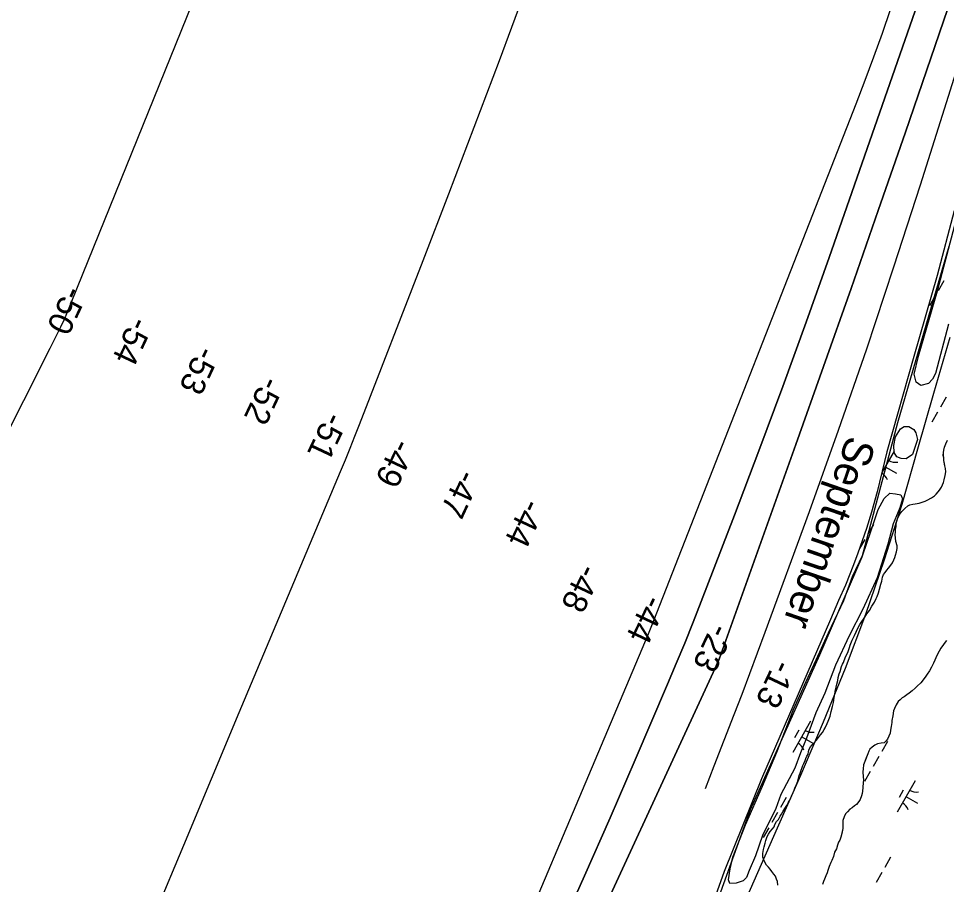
# Model space of a CAD drawing. Extents: x 3930721 to 3950824, y 220441 to 242861.
# Drawn here: x 3941164 to 3942447, y 230620 to 231818 of the extents above; entities that cross this region are included whole.
import ezdxf

# ---------------------------------------------------------------- set-up
doc = ezdxf.new("R2010")
doc.units = 0
for name, color, linetype in [('V-RIVR-EDGE', 7, 'Continuous'), ('V-RIVR-IDEN', 7, 'Continuous'), ('V-RIVR-JETY', 7, 'Continuous'), ('V-RIVR-RANG', 7, 'Continuous'), ('V-RRAP-FSHR', 7, 'Continuous'), ('V-TOPO-DPTH', 7, 'Continuous'), ('V-TOPO-MAJR', 7, 'Continuous'), ('V-TOPO-MINR', 7, 'Continuous'), ('V-TOPO-SHOR', 7, 'Continuous'), ('V-WETL-SWMP', 7, 'Continuous')]:
    doc.layers.add(name, color=color, linetype=linetype)

msp = doc.modelspace()

# ---------------------------------------------------------------- linework, layer by layer
at = {"layer": 'V-RIVR-EDGE'}
msp.add_lwpolyline([(3942450.4, 231502.1), (3942379.5, 231258.1), (3942329.9, 231072.3), (3942271.7, 230936.9), (3942175.7, 230722.8), (3942101.7, 230518.2), (3942078.1, 230444.2), (3941958.4, 230211.9), (3941798.6, 229866.4), (3941745.1, 229747.5)], dxfattribs=at)
at = {"layer": 'V-RIVR-JETY'}
for points in [[(3942450, 231394.6), (3942431.8, 231326.4), (3942428, 231318.9), (3942422.5, 231312.6), (3942411.9, 231310.1), (3942405.2, 231314.4), (3942402.7, 231325.7), (3942408.4, 231350.6), (3942435, 231440.9), (3942463, 231547.3)], [(3942407.2, 231235.3), (3942400.3, 231214.4), (3942391.3, 231208.4), (3942384.6, 231208.8), (3942378.7, 231211.1), (3942374.7, 231217.3), (3942374.2, 231226.7), (3942376.5, 231239), (3942383.4, 231250), (3942388.9, 231253.2), (3942395.2, 231253.3), (3942401.9, 231249), (3942404.7, 231244.4), (3942407.2, 231235.3)], [(3942211, 230724.5), (3942192.5, 230687.4), (3942183, 230659.3), (3942174.5, 230638.8), (3942170.7, 230629.3), (3942166, 230624.6), (3942156.2, 230621.3), (3942147.6, 230620.8), (3942145.6, 230625.9), (3942148.2, 230641.3), (3942151.9, 230657.4), (3942169.2, 230702.1), (3942192.6, 230755.4), (3942212.6, 230802.8), (3942235.6, 230861.6), (3942253.3, 230900.3), (3942267.1, 230930.3), (3942284.1, 230967.9), (3942305.2, 231012.5), (3942317.1, 231045.7), (3942331.7, 231075.7), (3942342.4, 231107.7), (3942352.7, 231138.4), (3942360.8, 231153.5), (3942369, 231161), (3942376.5, 231159.9), (3942384, 231158.8), (3942386.4, 231153.3), (3942382.6, 231140.7), (3942373.4, 231118.6), (3942366.2, 231090.6), (3942351.3, 231043.7), (3942331.7, 231000.6), (3942312.4, 230963.4), (3942293.9, 230923.1), (3942279, 230884.1), (3942266.7, 230857.2), (3942253.7, 230822.1), (3942245.2, 230801.5), (3942237.6, 230780.6), (3942218.3, 230744.2), (3942211, 230724.5)]]:
    msp.add_lwpolyline(points, dxfattribs=at)
at = {"layer": 'V-RRAP-FSHR'}
for points in [[(3942407.4, 231222.5), (3942429.6, 231299.3), (3942452.2, 231376.7)], [(3942019.7, 230258.7), (3942052.3, 230331.9), (3942084.4, 230405.7), (3942116.7, 230478.2), (3942149.1, 230551.4), (3942181.3, 230624.6), (3942213.6, 230697.8), (3942245.9, 230771), (3942277.3, 230844.6), (3942307.6, 230918.6), (3942335.7, 230993.5), (3942361.7, 231069.1), (3942385.7, 231145.6), (3942407.4, 231222.5)]]:
    msp.add_lwpolyline(points, dxfattribs=at)
at = {"layer": 'V-TOPO-DPTH'}
for points in [[(3942453.9, 231845.5), (3942443.3, 231814), (3942390.4, 231660.4), (3942352.9, 231552.2), (3942315.2, 231444.1), (3942277.2, 231336.1), (3942238.9, 231228.2), (3942137.6, 230944.3), (3942135.2, 230937.9), (3942132.6, 230931.4), (3942129.9, 230925.1), (3942127.1, 230918.8), (3941921, 230472.3), (3941888, 230401.2), (3941854.9, 230330.1), (3941821.4, 230259.2), (3941787.8, 230188.4), (3941758.8, 230127.6), (3941739.5, 230087.3), (3941720.2, 230046.9), (3941700.9, 230006.6), (3941681.6, 229966.3), (3941338.2, 229249.8)], [(3941491.1, 229651.3), (3941540.1, 229754), (3941663.9, 230015.8), (3941675, 230039.2), (3941685.9, 230062.7), (3941696.9, 230086.2), (3941707.7, 230109.7), (3941874.3, 230471.6), (3941910.6, 230551.4), (3941946.5, 230631.4), (3941981.8, 230711.7), (3942016.7, 230792.2), (3942061.5, 230896.6), (3942073.5, 230925.1), (3942085.4, 230953.6), (3942096.8, 230982.4), (3942108.1, 231011.2), (3942154.1, 231130.7), (3942187.7, 231219.4), (3942220.8, 231308.4), (3942253.1, 231397.7), (3942284.8, 231487.2), (3942410.7, 231848.7)], [(3942410.7, 231848.7), (3942284.8, 231487.2), (3942253.1, 231397.7), (3942220.8, 231308.4), (3942187.7, 231219.4), (3942154.1, 231130.7), (3942108.1, 231011.2), (3942096.8, 230982.4), (3942085.4, 230953.6), (3942073.5, 230925.1), (3942061.5, 230896.6), (3942016.7, 230792.2), (3941981.8, 230711.7), (3941946.5, 230631.4), (3941910.6, 230551.4), (3941874.3, 230471.6), (3941707.7, 230109.7), (3941696.9, 230086.2), (3941685.9, 230062.7), (3941675, 230039.2), (3941663.9, 230015.8), (3941540.1, 229754), (3941491.1, 229651.3)], [(3941769.9, 230338.3), (3942035, 230966.4), (3942036.9, 230971), (3942038.8, 230975.5), (3942040.7, 230980.1), (3942042.5, 230984.8), (3942322.4, 231699.8), (3942334.8, 231732.3), (3942346.9, 231764.8), (3942358.6, 231797.5), (3942369.9, 231830.3)], [(3941769.9, 230338.3), (3942035, 230966.4), (3942036.9, 230971), (3942038.8, 230975.5), (3942040.7, 230980.1), (3942042.5, 230984.8), (3942322.4, 231699.8), (3942334.8, 231732.3), (3942346.9, 231764.8), (3942358.6, 231797.5), (3942369.9, 231830.3)]]:
    msp.add_lwpolyline(points, dxfattribs=at)
at = {"layer": 'V-TOPO-MAJR'}
for points in [[(3941426.2, 231894.7), (3941229.1, 231406.6), (3941228.6, 231405.4), (3941228.3, 231404.8), (3941228, 231404.2), (3941221.5, 231390.5), (3941217.9, 231383.1), (3941214.3, 231375.7), (3941210.6, 231368.3), (3941206.9, 231361), (3940805.4, 230563.5), (3940792.7, 230537.9), (3940780.1, 230512.3), (3940767.7, 230486.5), (3940755.5, 230460.7), (3940592.2, 230110.7), (3940552.6, 230025.6), (3940513.2, 229940.4), (3940474.1, 229855.1), (3940435.2, 229769.8), (3940389.8, 229670)], [(3941354, 230582.4), (3941392.3, 230674.1), (3941430.6, 230765.7), (3941469, 230857.3), (3941609.1, 231190.9), (3941615.8, 231207.2), (3941622.4, 231223.4), (3941628.9, 231239.7), (3941635.4, 231256.1), (3941723.4, 231482.8), (3941758.9, 231575), (3941794.1, 231667.3), (3941828.7, 231759.8), (3941863, 231852.4)]]:
    msp.add_lwpolyline(points, dxfattribs=at)
at = {"layer": 'V-TOPO-MINR'}
for points in [[(3941338.2, 229249.8), (3941681.6, 229966.3), (3941700.9, 230006.6), (3941720.2, 230046.9), (3941739.5, 230087.3), (3941758.8, 230127.6), (3941787.8, 230188.4), (3941821.4, 230259.2), (3941854.9, 230330.1), (3941888, 230401.2), (3941921, 230472.3), (3942127.1, 230918.8), (3942129.9, 230925.1), (3942132.6, 230931.4), (3942135.2, 230937.9), (3942137.6, 230944.3), (3942238.9, 231228.2), (3942277.2, 231336.1), (3942315.2, 231444.1), (3942352.9, 231552.2), (3942390.4, 231660.4), (3942443.3, 231814), (3942453.9, 231845.5)], [(3941491.1, 229651.3), (3941540.1, 229754), (3941663.9, 230015.8), (3941675, 230039.2), (3941685.9, 230062.7), (3941696.9, 230086.2), (3941707.7, 230109.7), (3941874.3, 230471.6), (3941910.6, 230551.4), (3941946.5, 230631.4), (3941981.8, 230711.7), (3942016.7, 230792.2), (3942061.5, 230896.6), (3942073.5, 230925.1), (3942085.4, 230953.6), (3942096.8, 230982.4), (3942108.1, 231011.2), (3942154.1, 231130.7), (3942187.7, 231219.4), (3942220.8, 231308.4), (3942253.1, 231397.7), (3942284.8, 231487.2), (3942410.7, 231848.7)], [(3942113.7, 230752.2), (3942125.9, 230783.8), (3942153.4, 230854.6), (3942164.4, 230883), (3942175.2, 230911.4), (3942185.9, 230939.9), (3942196.4, 230968.5), (3942257.5, 231135.6), (3942297.7, 231248), (3942336.9, 231360.8), (3942374.6, 231474.1), (3942411.3, 231587.7), (3942493.9, 231849.4)], [(3941769.9, 230338.3), (3942035, 230966.4), (3942036.9, 230971), (3942038.8, 230975.5), (3942040.7, 230980.1), (3942042.5, 230984.8), (3942322.4, 231699.8), (3942334.8, 231732.3), (3942346.9, 231764.8), (3942358.6, 231797.5), (3942369.9, 231830.3)]]:
    msp.add_lwpolyline(points, dxfattribs=at)
at = {"layer": 'V-TOPO-SHOR'}
for points in [[(3942270.3, 230822.9), (3942273.1, 230826.7), (3942275.5, 230829.9), (3942277.9, 230833.8), (3942279.6, 230836.2), (3942282.3, 230842.2), (3942283.7, 230845.7), (3942286.1, 230852.4), (3942287.8, 230859), (3942289.4, 230866), (3942291.1, 230871.3), (3942291.4, 230874.5), (3942291.8, 230878.3), (3942292.8, 230882.9), (3942293.4, 230886.4), (3942294.8, 230892.7), (3942295.4, 230896.5), (3942296.8, 230901.8), (3942297.4, 230906), (3942298.8, 230910.9), (3942300.1, 230914.4), (3942302.2, 230921), (3942303.2, 230924.2), (3942304.9, 230926.7), (3942307.6, 230934.4), (3942310.7, 230940.7), (3942313.1, 230947.4), (3942314.1, 230950.5), (3942316.8, 230957.5), (3942318.2, 230960.4), (3942319.9, 230964.2), (3942321.3, 230967), (3942323.3, 230971.2), (3942325.7, 230976.2), (3942327.4, 230979.3), (3942330.2, 230983.5), (3942332.2, 230986.7), (3942334.3, 230989.2), (3942337.1, 230993.8), (3942340.5, 230998.7), (3942344, 231004.7), (3942347.7, 231010.3), (3942349.8, 231015.2), (3942351.2, 231018), (3942353.2, 231022.9), (3942354.5, 231028.2), (3942356.6, 231035.2), (3942357.6, 231039.1), (3942358.9, 231044.7), (3942360.3, 231048.5), (3942362.4, 231051), (3942364.8, 231054.2), (3942367.2, 231057), (3942370.3, 231061.2), (3942372.4, 231064.7), (3942374.4, 231068.6), (3942375.8, 231072.1), (3942376.8, 231075.2), (3942378.1, 231079.8), (3942378.8, 231084.4), (3942378.8, 231088.2), (3942377.3, 231094.1), (3942376.9, 231099), (3942376.2, 231103.2), (3942376.8, 231107.1), (3942376.8, 231110.9), (3942377.4, 231114.4), (3942377.8, 231118.2), (3942378.4, 231122.1), (3942380.1, 231127), (3942382.9, 231131.9), (3942385.6, 231135.5), (3942389.4, 231139.7), (3942393.9, 231143.6), (3942396.7, 231145), (3942400.5, 231145.7), (3942403.7, 231146.1), (3942409.6, 231147.2), (3942413.5, 231148.3), (3942417.6, 231149.8), (3942420.4, 231151.2), (3942426.3, 231154.4), (3942430.5, 231157.2), (3942432.9, 231159.7), (3942435.7, 231162.9), (3942437.7, 231165.3), (3942440.2, 231169.2), (3942442.9, 231175.5), (3942444.2, 231179.4), (3942445.6, 231185.3), (3942446.2, 231190.6), (3942445.8, 231195.1), (3942445.1, 231198.6), (3942444.4, 231202.5), (3942443.6, 231206.3), (3942443.6, 231209.4), (3942442.9, 231213.6), (3942443.2, 231217.1), (3942443.5, 231220.3), (3942444.5, 231224.8), (3942446.2, 231229.4)], [(3942446.2, 231229.4), (3942448.6, 231234.3)], [(3942447.2, 230957.1), (3942445.5, 230954.7), (3942443.1, 230951.5), (3942439.6, 230946.6), (3942437.2, 230942.3), (3942434.5, 230937.1), (3942432.4, 230932.9), (3942431, 230930), (3942429.3, 230925.8), (3942426.6, 230920.2), (3942423.5, 230915.3), (3942420.7, 230910.7), (3942418.7, 230907.9), (3942414.9, 230902.6), (3942411.8, 230898.4), (3942406.6, 230893.8), (3942403.8, 230891.3), (3942399.7, 230887.4), (3942395.5, 230884.2), (3942392.4, 230881.8), (3942388.9, 230879.3), (3942385.8, 230877.9), (3942383, 230875), (3942380.6, 230872.6), (3942377.5, 230868), (3942375.4, 230863.1), (3942374.1, 230859.6), (3942373.1, 230852.9), (3942371.8, 230846.6), (3942371.4, 230843.5), (3942370.8, 230837.9), (3942369.8, 230833), (3942369.2, 230828.8), (3942367.4, 230824.9), (3942365.7, 230820.7), (3942363.7, 230818.2), (3942360.9, 230815.7), (3942356.7, 230815), (3942351.8, 230813.9), (3942348, 230812.1), (3942344.5, 230809.6), (3942341.4, 230806.8), (3942340, 230804), (3942338.3, 230800.1), (3942336.3, 230794.9), (3942334.2, 230789.6), (3942332.5, 230785), (3942331.9, 230779.4), (3942331.6, 230775.2), (3942332, 230768.6), (3942332.4, 230764.1), (3942332.1, 230760.6), (3942331.5, 230753.9), (3942331.2, 230748.7), (3942330.5, 230745.5), (3942329.5, 230742), (3942327.8, 230737.1), (3942326.1, 230734.3), (3942322.6, 230730.4), (3942319.8, 230728.3), (3942316.7, 230725.8), (3942313.6, 230723.7), (3942310.1, 230720.2), (3942307.7, 230717.3), (3942305.7, 230713.1), (3942304, 230707.9), (3942303.7, 230704), (3942303.7, 230700.9), (3942303.7, 230697), (3942303.1, 230693.5), (3942302.4, 230690), (3942301, 230685.1), (3942299.7, 230680.9), (3942298, 230678.1), (3942296.6, 230673.9), (3942294.9, 230669), (3942292.5, 230664.1), (3942290.8, 230658.4), (3942288.4, 230652.8), (3942287.4, 230649.7), (3942285, 230644.4), (3942283.3, 230638.8), (3942282, 230635.6), (3942280.3, 230631.4), (3942278.6, 230626.9), (3942277.2, 230623.7), (3942275.5, 230619.5)], [(3942214.1, 230618.7), (3942213.3, 230623.5), (3942212.3, 230627), (3942210.5, 230630.9), (3942208.3, 230634), (3942205.5, 230637.4), (3942203.4, 230640.9), (3942200.9, 230643.3), (3942198.4, 230646.1), (3942196.3, 230649.6), (3942194.5, 230653.8), (3942193.4, 230657.3), (3942193.3, 230662.2), (3942194, 230667.7), (3942195, 230671.8), (3942196.3, 230676.9), (3942197.3, 230680.6), (3942199.4, 230685.7), (3942201.1, 230689), (3942203.5, 230692.9), (3942206.6, 230696.7), (3942208.7, 230699.4), (3942209.7, 230702.3), (3942212.2, 230706.5), (3942214.7, 230709.6), (3942217.1, 230714.2), (3942219.1, 230716.8), (3942220.9, 230720), (3942223.6, 230724.5), (3942226.4, 230729), (3942228.8, 230733.5), (3942230.5, 230736.2), (3942231.9, 230739.4), (3942233.3, 230743.3), (3942235, 230746.9), (3942236.4, 230750), (3942238.1, 230754.1), (3942239.9, 230757.8), (3942241.6, 230762.6), (3942242.6, 230766.4), (3942243.6, 230770.1), (3942244.6, 230773.6), (3942246.3, 230777.9), (3942247.7, 230781.3), (3942248.7, 230784.3), (3942250, 230787.1), (3942251.8, 230790.9), (3942252.8, 230794), (3942254.1, 230796.9), (3942255.9, 230800), (3942256.5, 230803.3), (3942257.2, 230806.6), (3942258.9, 230809.8), (3942261.3, 230812.6), (3942263.7, 230815.1), (3942267.2, 230819), (3942270.3, 230822.9)]]:
    msp.add_lwpolyline(points, dxfattribs=at)
at = {"layer": 'V-WETL-SWMP'}
for p, q in [((3942443.4, 231454.9), (3942435.5, 231441.1)), ((3942431.5, 231434.1), (3942423.5, 231420.2)), ((3942446.9, 231293.9), (3942439, 231280)), ((3942435, 231273.1), (3942427, 231259.2)), ((3942374.9, 231219.2), (3942357.9, 231189.5)), ((3942362.5, 231197.5), (3942378.1, 231188.5)), ((3942346.1, 231117.8), (3942338.1, 231103.9)), ((3942334.1, 231097), (3942326.9, 231084.2)), ((3942259.3, 230845.5), (3942234.5, 230802.1)), ((3942243.2, 230832.9), (3942237.2, 230822.4)), ((3942246.9, 230823.8), (3942262.5, 230814.9)), ((3942365.7, 230817.3), (3942357.7, 230803.5)), ((3942353.8, 230796.5), (3942345.8, 230782.6)), ((3942341.8, 230775.7), (3942333.9, 230761.8)), ((3942403.7, 230762.8), (3942378.8, 230719.5)), ((3942225.5, 230739.8), (3942217.6, 230725.9)), ((3942387.5, 230750.2), (3942381.6, 230739.8)), ((3942391.2, 230741.1), (3942406.9, 230732.2)), ((3942213.6, 230719), (3942205.6, 230705.1)), ((3942201.7, 230698.1), (3942193.7, 230684.3)), ((3942369.9, 230657.1), (3942361.9, 230643.2)), ((3942357.9, 230636.3), (3942350, 230622.4))]:
    msp.add_line(p, q, dxfattribs=at)
for points in [[(3942457.8, 231551.4), (3942434.2, 231462), (3942402, 231350.2), (3942364.8, 231218), (3942351.4, 231162.8), (3942343.7, 231134.7), (3942336.5, 231112.2), (3942324.7, 231078), (3942318.6, 231061.9), (3942307.4, 231033.8)], [(3942298.8, 230910.9), (3942300.1, 230914.4), (3942302.2, 230921), (3942303.2, 230924.2), (3942304.9, 230926.7), (3942307.6, 230934.4), (3942310.7, 230940.7), (3942313.1, 230947.4), (3942314.1, 230950.5), (3942316.8, 230957.5), (3942318.2, 230960.4), (3942319.9, 230964.2), (3942325.7, 230976.2), (3942327.4, 230979.3), (3942332.2, 230986.7), (3942334.3, 230989.2), (3942337.1, 230993.8), (3942340.5, 230998.7), (3942344, 231004.7), (3942347.7, 231010.3), (3942349.8, 231015.2), (3942351.2, 231018), (3942353.2, 231022.9), (3942354.5, 231028.2), (3942356.6, 231035.2), (3942357.6, 231039.1), (3942358.9, 231044.7), (3942360.3, 231048.5), (3942362.4, 231051), (3942364.8, 231054.2), (3942367.2, 231057), (3942370.3, 231061.2), (3942372.4, 231064.7), (3942374.4, 231068.6), (3942375.8, 231072.1), (3942376.8, 231075.2), (3942378.1, 231079.8), (3942378.8, 231084.4), (3942378.8, 231088.2), (3942377.3, 231094.1), (3942376.9, 231099), (3942376.2, 231103.2), (3942376.8, 231107.1), (3942376.8, 231110.9), (3942377.4, 231114.4), (3942377.8, 231118.2), (3942378.4, 231122.1), (3942380.1, 231127), (3942382.9, 231131.9), (3942385.6, 231135.5), (3942389.4, 231139.7), (3942393.9, 231143.6), (3942396.7, 231145), (3942400.5, 231145.7), (3942403.7, 231146.1), (3942409.6, 231147.2), (3942413.5, 231148.3), (3942417.6, 231149.8), (3942420.4, 231151.2), (3942426.3, 231154.4), (3942430.5, 231157.2), (3942432.9, 231159.7), (3942435.7, 231162.9), (3942437.7, 231165.3), (3942440.2, 231169.2), (3942442.9, 231175.5), (3942444.2, 231179.4), (3942445.6, 231185.3), (3942446.2, 231190.6), (3942445.8, 231195.1), (3942445.1, 231198.6), (3942443.6, 231206.3), (3942443.6, 231209.4), (3942442.8, 231213.6), (3942443.2, 231217.1), (3942443.5, 231220.3), (3942444.5, 231224.8), (3942446.2, 231229.4), (3942448.6, 231234.3)], [(3942307.4, 231033.8), (3942297.8, 231012.4), (3942286.7, 230986.2), (3942191.4, 230765.7), (3942139.9, 230637.5), (3942089.8, 230497.5), (3942052, 230404), (3942027.8, 230351), (3942014.1, 230324.5), (3942000.3, 230299.2), (3941931.2, 230166.6), (3941841.8, 229965.3), (3941759.9, 229782.5), (3941694.3, 229632.9)], [(3942447.2, 230957.1), (3942445.5, 230954.7), (3942443.1, 230951.5), (3942439.6, 230946.6), (3942437.2, 230942.3), (3942434.5, 230937.1), (3942431, 230930), (3942429.3, 230925.8), (3942426.6, 230920.2), (3942423.5, 230915.3), (3942420.7, 230910.7), (3942418.7, 230907.9), (3942414.9, 230902.6), (3942411.8, 230898.4), (3942406.6, 230893.8), (3942403.8, 230891.3), (3942399.7, 230887.4), (3942395.5, 230884.2), (3942392.4, 230881.8), (3942388.9, 230879.3), (3942385.8, 230877.9), (3942380.6, 230872.6), (3942377.5, 230868), (3942375.4, 230863.1), (3942374.1, 230859.6)], [(3942214.1, 230618.7), (3942213.3, 230623.5), (3942212.3, 230627), (3942210.5, 230630.9), (3942208.3, 230634), (3942205.5, 230637.4), (3942203.4, 230640.9), (3942200.9, 230643.3), (3942198.4, 230646.1), (3942196.3, 230649.6), (3942194.5, 230653.8), (3942193.4, 230657.3), (3942193.3, 230662.2), (3942194, 230667.7), (3942195, 230671.8), (3942196.3, 230676.9), (3942197.3, 230680.6), (3942199.4, 230685.7), (3942201.1, 230689), (3942203.5, 230692.9), (3942206.6, 230696.7), (3942208.7, 230699.4), (3942209.7, 230702.3), (3942212.2, 230706.5), (3942214.7, 230709.6), (3942217.1, 230714.2), (3942219.1, 230716.8), (3942220.9, 230720), (3942226.4, 230729), (3942228.8, 230733.5), (3942230.5, 230736.2), (3942231.9, 230739.4), (3942233.3, 230743.3), (3942235, 230746.9), (3942236.4, 230750), (3942238.1, 230754.1), (3942239.9, 230757.8), (3942241.6, 230762.5), (3942242.6, 230766.4), (3942243.6, 230770.1), (3942244.6, 230773.6), (3942246.3, 230777.9), (3942247.7, 230781.3), (3942248.7, 230784.3), (3942250, 230787.1), (3942251.8, 230790.9), (3942252.8, 230794), (3942254.1, 230796.9), (3942255.9, 230800), (3942256.5, 230803.3), (3942257.2, 230806.6), (3942258.9, 230809.8), (3942261.3, 230812.6), (3942263.7, 230815.1), (3942267.2, 230819), (3942270.3, 230822.9), (3942273.1, 230826.7), (3942275.5, 230829.9), (3942277.9, 230833.8), (3942279.6, 230836.2), (3942282.3, 230842.2), (3942283.7, 230845.7), (3942286.1, 230852.4), (3942287.8, 230859), (3942289.4, 230866), (3942291.1, 230871.3), (3942291.4, 230874.5), (3942291.8, 230878.3), (3942292.8, 230882.9), (3942293.4, 230886.4), (3942294.8, 230892.7), (3942295.4, 230896.5), (3942296.8, 230901.8), (3942297.4, 230906), (3942298.8, 230910.9)], [(3942374.1, 230859.6), (3942373.1, 230852.9), (3942371.8, 230846.6), (3942371.4, 230843.5), (3942370.8, 230837.9), (3942369.8, 230833), (3942369.1, 230828.8), (3942367.4, 230824.9), (3942365.7, 230820.7), (3942363.7, 230818.2), (3942360.9, 230815.7), (3942356.7, 230815), (3942351.8, 230813.9), (3942348, 230812.1), (3942344.5, 230809.6), (3942341.4, 230806.8), (3942340, 230804), (3942338.3, 230800.1), (3942334.2, 230789.6), (3942332.5, 230785), (3942331.9, 230779.4), (3942331.6, 230775.2), (3942332, 230768.6), (3942332.4, 230764.1), (3942332.1, 230760.6), (3942331.5, 230753.9), (3942331.2, 230748.7), (3942330.5, 230745.5), (3942329.5, 230742), (3942327.8, 230737.1), (3942326.1, 230734.3), (3942322.6, 230730.4), (3942319.8, 230728.3), (3942316.7, 230725.8), (3942313.6, 230723.7), (3942310.1, 230720.2), (3942307.7, 230717.3), (3942305.7, 230713.1), (3942304, 230707.9), (3942303.7, 230704), (3942303.7, 230697), (3942302.4, 230690), (3942301, 230685.1), (3942299.7, 230680.9), (3942298, 230678.1), (3942296.6, 230673.9), (3942294.9, 230669), (3942292.5, 230664.1), (3942290.8, 230658.4), (3942288.4, 230652.8), (3942287.4, 230649.7), (3942285, 230644.4), (3942283.3, 230638.8), (3942282, 230635.6), (3942280.3, 230631.4), (3942278.6, 230626.9), (3942277.2, 230623.7), (3942275.5, 230619.5)]]:
    msp.add_lwpolyline(points, dxfattribs=at)
for centre, start, end in [((3942376.4, 231221.3), 239.4279, 280.9715), ((3942348.9, 231173.4), 19.4279, 60.2056), ((3942260.8, 230847.7), 239.4279, 280.9715), ((3942233.4, 230799.7), 19.4279, 60.9715), ((3942405.2, 230765), 239.4279, 280.9715), ((3942377.7, 230717.1), 19.4279, 60.9715)]:
    msp.add_arc(centre, 17.6, start, end, dxfattribs=at)

# ---------------------------------------------------------------- texts
at = {"layer": 'V-RIVR-IDEN'}
msp.add_text('September', height=42, rotation=250.9407, dxfattribs=at).set_placement((3942310.5, 231242.5))
at = {"layer": 'V-RIVR-RANG'}
for s, rotation, p in [('-50', 244.8283, (3941229.5, 231449.8)), ('-54', 244.8283, (3941320.5, 231407.2)), ('-53', 244.8283, (3941412.7, 231366.5)), ('-52', 244.8283, (3941502.2, 231324.8)), ('-51', 244.8283, (3941589.7, 231275.3)), ('-49', 244.8283, (3941683.8, 231238.2)), ('-47', 244.8283, (3941773.6, 231195.7)), ('-44', 244.8283, (3941863.2, 231155.3)), ('-48', 244.6883, (3941941.1, 231065.1)), ('-44', 244.6883, (3942031.5, 231022.2)), ('-23', 244.6883, (3942123.4, 230982.6)), ('-13', 244.6883, (3942210.3, 230932.5))]:
    msp.add_text(s, height=33.5, rotation=rotation, dxfattribs=at).set_placement(p)

doc.saveas('drawing.dxf')
